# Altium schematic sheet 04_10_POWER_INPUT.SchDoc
size 289 x 396 mm
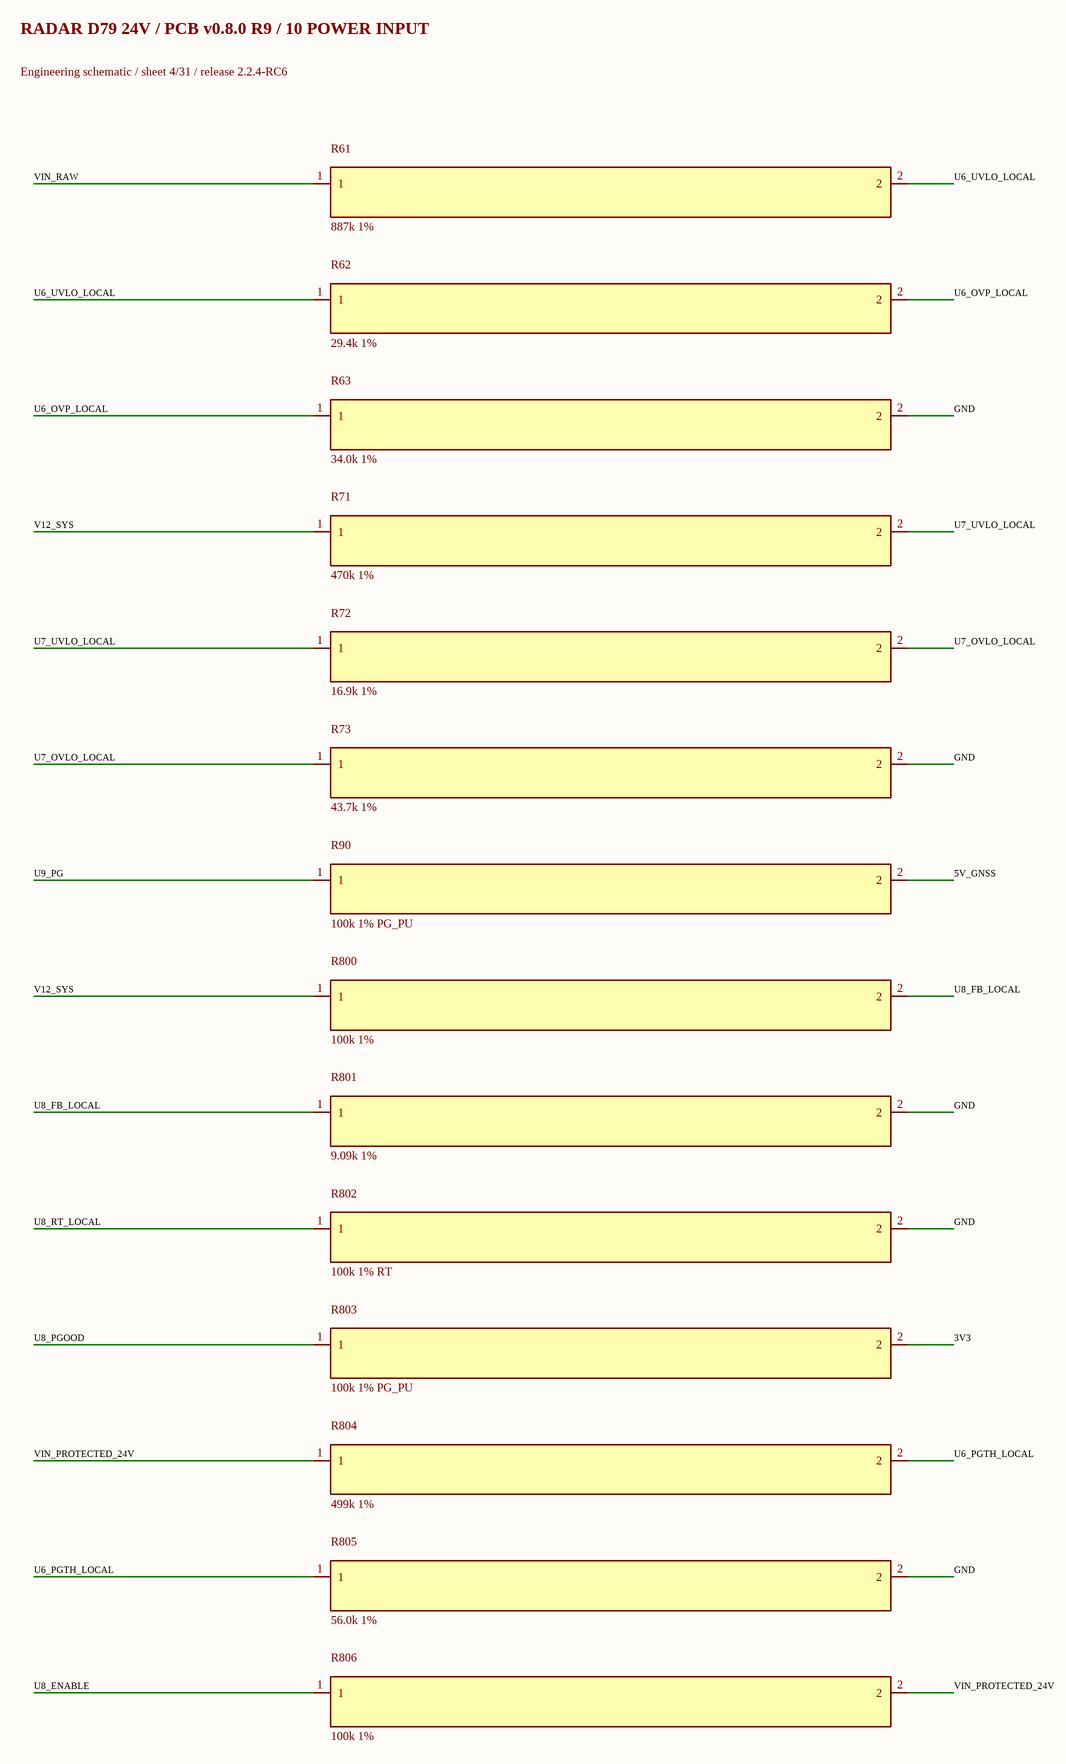
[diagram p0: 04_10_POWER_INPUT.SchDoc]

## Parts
R61  887k 1%  [R_0603_1608Metric]
R62  29.4k 1%  [R_0603_1608Metric]
R63  34.0k 1%  [R_0603_1608Metric]
R71  470k 1%  [R_0603_1608Metric]
R72  16.9k 1%  [R_0603_1608Metric]
R73  43.7k 1%  [R_0603_1608Metric]
R90  100k 1% PG_PU  [R_0603_1608Metric]
R800  100k 1%  [R_0603_1608Metric]
R801  9.09k 1%  [R_0603_1608Metric]
R802  100k 1% RT  [R_0603_1608Metric]
R803  100k 1% PG_PU  [R_0603_1608Metric]
R804  499k 1%  [R_0603_1608Metric]
R805  56.0k 1%  [R_0603_1608Metric]
R806  100k 1%  [R_0603_1608Metric]

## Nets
3V3: R803.2
5V_GNSS: R90.2
GND: R63.2 R73.2 R801.2 R802.2 R805.2
U6_OVP_LOCAL: R62.2 R63.1
U6_PGTH_LOCAL: R804.2 R805.1
U6_UVLO_LOCAL: R61.2 R62.1
U7_OVLO_LOCAL: R72.2 R73.1
U7_UVLO_LOCAL: R71.2 R72.1
U8_ENABLE: R806.1
U8_FB_LOCAL: R800.2 R801.1
U8_PGOOD: R803.1
U8_RT_LOCAL: R802.1
U9_PG: R90.1
V12_SYS: R71.1 R800.1
VIN_PROTECTED_24V: R804.1 R806.2
VIN_RAW: R61.1

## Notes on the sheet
- RADAR D79 24V / PCB v0.8.0 R9 / 10 POWER INPUT
- Engineering schematic / sheet 4/31 / release 2.2.4-RC6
